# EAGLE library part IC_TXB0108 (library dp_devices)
8-Bit bidirectional voltage level translator Mfr no: TXB0108PWR TXB0108PWR
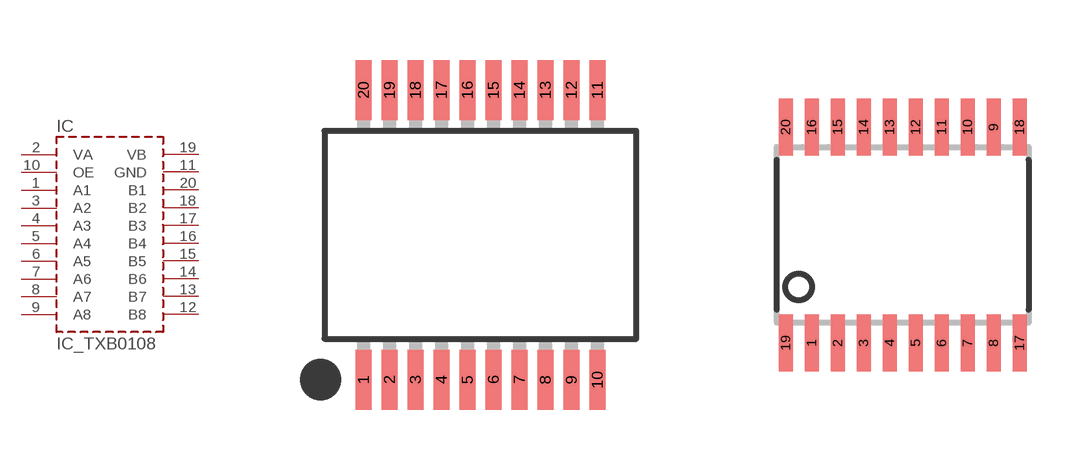
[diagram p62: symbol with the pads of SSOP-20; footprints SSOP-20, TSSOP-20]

Designator prefix IC

## IC_TXB0108PW  [SSOP-20]
1  A1
2  VA
3  A2
4  A3
5  A4
6  A5
7  A6
8  A7
9  A8
10  OE
11  GND
12  B8
13  B7
14  B6
15  B5
16  B4
17  B3
18  B2
19  VB
20  B1

## IC_TXB0108-TSSOP-20  [TSSOP-20]
Pads as for SSOP-20

## Footprint SSOP-20 (pad centres in mm)
smd 0.4 x 1.5: 1 -2.925,-3.625; 2 -2.275,-3.625; 3 -1.625,-3.625; 4 -0.975,-3.625; 5 -0.325,-3.625; 6 0.325,-3.625; 7 0.975,-3.625; 8 1.625,-3.625; 9 2.275,-3.625; 10 2.925,-3.625; 11 2.925,3.625; 12 2.275,3.625; 13 1.625,3.625; 14 0.975,3.625; 15 0.325,3.625; 16 -0.325,3.625; 17 -0.975,3.625; 18 -1.625,3.625; 19 -2.275,3.625; 20 -2.925,3.625

## Footprint TSSOP-20 (pad centres in mm)
Pad size: 0.35 x 1.43 mm Pad pitch: 0.65 mm Pad lateral pitch: 5.4 mm
smd 0.35 x 1.43: 1 -2.275,-2.7; 2 -1.625,-2.7; 3 -0.975,-2.7; 4 -0.325,-2.7; 5 0.325,-2.7; 6 0.975,-2.7; 7 1.625,-2.7; 8 2.275,-2.7; 9 2.275,2.7; 10 1.625,2.7; 11 0.975,2.7; 12 0.325,2.7; 13 -0.325,2.7; 14 -0.975,2.7; 15 -1.625,2.7; 16 -2.275,2.7; 17 2.925,-2.7; 18 2.925,2.7; 19 -2.925,-2.7; 20 -2.925,2.7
